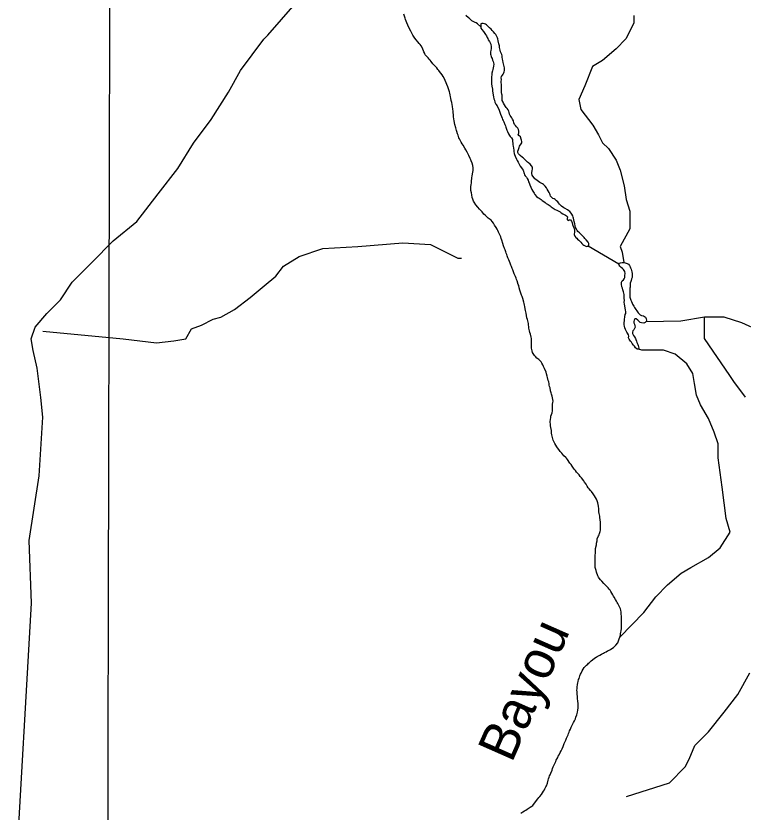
# Model space of a CAD drawing. Extents: x 3192927 to 3230760, y 831141 to 856475.
# Drawn here: x 3202099 to 3203997, y 838498 to 840576 of the extents above; entities that cross this region are included whole.
import ezdxf

# ---------------------------------------------------------------- set-up
doc = ezdxf.new("R2010")
doc.units = 0
for name, color, linetype in [('V-GRID-MAJR', 7, 'Continuous'), ('V-RIVR-IDEN', 7, 'Continuous'), ('V-TOPO-SHOR', 7, 'Continuous')]:
    doc.layers.add(name, color=color, linetype=linetype)

msp = doc.modelspace()

# ---------------------------------------------------------------- linework, layer by layer
at = {"layer": 'V-GRID-MAJR'}
msp.add_spline([(3202335.2, 836536.2), (3202348.4, 842596.7), (3202361.7, 848659.1), (3202374.9, 854721.5), (3202374.9, 854723.4)], degree=3, dxfattribs=at)
at = {"layer": 'V-TOPO-SHOR'}
msp.add_line((3203672.2, 839927.9), (3203592.4, 839974.9), dxfattribs=at)
for points in [[(3202099.2, 838328.4), (3202139.5, 839043.4), (3202134.2, 839206.8), (3202159.6, 839375.4), (3202169.7, 839528.6), (3202164.6, 839579.7), (3202154.3, 839656.3), (3202144, 839702.2), (3202138.9, 839732.9), (3202149.1, 839763.5), (3202179.7, 839799.3), (3202215.4, 839835.1), (3202246, 839881.1), (3202297.1, 839932.2), (3202353.2, 839988.4), (3202414.4, 840039.5), (3202470.6, 840111.1), (3202521.6, 840177.5), (3202562.4, 840243.9), (3202608.3, 840305.3), (3202654.2, 840376.8), (3202684.8, 840433), (3202746, 840514.8), (3202756.2, 840525), (3202827.7, 840606.8)], [(3203197.5, 840439.8), (3203190.9, 840447.4), (3203187.5, 840450.9), (3203182.7, 840456.6), (3203179.9, 840460.4), (3203177.9, 840462.7), (3203174.5, 840466.1), (3203167.3, 840474.3), (3203165.9, 840477.2), (3203163.9, 840482.2), (3203159.8, 840491.6), (3203156.5, 840497.8), (3203154.1, 840501), (3203151.3, 840503.9), (3203140.3, 840517.8), (3203134.9, 840525.5), (3203130, 840535.7), (3203123.7, 840546.8), (3203117.3, 840561.6), (3203115.5, 840566.4), (3203114.8, 840569.7), (3203111.7, 840579.8)], [(3203312.2, 840547.1), (3203304, 840555.3), (3203300.1, 840557.3), (3203297.2, 840558.4), (3203288.5, 840563.1), (3203282.7, 840568.6), (3203280.2, 840570.5), (3203273.6, 840576.7)], [(3203711.2, 840576.8), (3203711.3, 840556.4), (3203690.9, 840515.5), (3203665.3, 840490), (3203629.6, 840459.3), (3203604.1, 840444), (3203583.7, 840392.9), (3203568.4, 840357.1), (3203573.5, 840331.6), (3203604.2, 840290.8), (3203619.6, 840265.2), (3203629.8, 840244.8), (3203645.1, 840229.5), (3203665.6, 840198.9), (3203675.8, 840173.4), (3203686.1, 840132.5), (3203691.2, 840096.8), (3203701.4, 840066.1), (3203701.5, 840035.5), (3203701.5, 840020.2), (3203676, 839974.2), (3203681.1, 839958.9), (3203685.4, 839931.9)], [(3203412, 840232.1), (3203413.4, 840235.5), (3203418, 840241.9), (3203419, 840244.8), (3203419, 840248.3), (3203418.5, 840251.4), (3203417.6, 840254.3), (3203415.7, 840259.8), (3203411.9, 840263.2), (3203410.2, 840266), (3203411.6, 840269.4), (3203411.6, 840275.3), (3203410.5, 840279.4), (3203409.3, 840282.3), (3203405.7, 840285.9), (3203402.9, 840289.5), (3203400.2, 840292.1), (3203398.1, 840296.9), (3203397.6, 840301.4), (3203395.3, 840306), (3203393.1, 840309.3), (3203391.5, 840312.2), (3203388.6, 840315.8), (3203387, 840319.1), (3203386, 840323.2), (3203385.3, 840326.8), (3203383.4, 840330.6), (3203381, 840334.2), (3203378.9, 840336.8), (3203377, 840339.4), (3203374.4, 840343.3), (3203371.8, 840347.8), (3203370.3, 840350.7), (3203368.4, 840354.5), (3203368, 840358.1), (3203368, 840364.1), (3203367.8, 840368.4), (3203366.8, 840371.7), (3203366.1, 840375.5), (3203365.9, 840379.3), (3203366.4, 840382.4), (3203366.4, 840386.7), (3203366.4, 840391.3), (3203366.2, 840394.6), (3203366, 840397.7), (3203365.7, 840401.1), (3203365.7, 840404.7), (3203366, 840409.9), (3203365.8, 840413.7), (3203366.7, 840417.1), (3203368.6, 840420.9), (3203370.6, 840424), (3203372, 840426.8), (3203373.2, 840429.7), (3203373.9, 840432.8), (3203374.4, 840436.6), (3203374.4, 840440), (3203373.3, 840444), (3203371.6, 840450.5), (3203370.9, 840454.1), (3203369.7, 840459.3), (3203368.8, 840463.1), (3203368.1, 840467.7), (3203367.6, 840471.5), (3203366.9, 840474.6), (3203365, 840478.7), (3203363.3, 840482), (3203362.4, 840486.1), (3203361.7, 840489.4), (3203361.5, 840493.5), (3203360.8, 840497.8), (3203359.6, 840502.8), (3203357.7, 840510.2), (3203356.5, 840515.7), (3203355.6, 840518.8), (3203354.4, 840521.7), (3203351.3, 840526.7), (3203348.7, 840530), (3203345.1, 840534.1), (3203342, 840537.7), (3203339.4, 840540.8), (3203335.1, 840544.9), (3203332.8, 840547), (3203330.4, 840549.2), (3203327, 840552.1), (3203324.4, 840553.8), (3203321.6, 840555.2), (3203318.5, 840555.7), (3203315.3, 840555.7), (3203312.5, 840554.5), (3203312.2, 840551.4), (3203312.2, 840547.1), (3203312.7, 840543.5), (3203315.1, 840539.9), (3203318.9, 840535.2), (3203322.9, 840530.1), (3203324.8, 840527.5), (3203327.2, 840523.4), (3203328.8, 840519.6), (3203330.3, 840516.5), (3203331.7, 840512.9)], [(3203331.7, 840512.9), (3203335, 840508.4), (3203336.9, 840505.5), (3203338.3, 840502.1), (3203339, 840494.5), (3203339, 840490.2), (3203338.3, 840485.7), (3203337.8, 840482.3), (3203337.3, 840479), (3203337.8, 840475.9), (3203338.2, 840472.8), (3203339.2, 840469.9), (3203340.1, 840467), (3203341.6, 840464.2), (3203342.7, 840460.1), (3203342.9, 840459.9)], [(3203342.9, 840459.9), (3203344.4, 840457), (3203345.6, 840453.2), (3203346.1, 840449.8), (3203345.6, 840444.3), (3203343.6, 840436), (3203342.7, 840432.4), (3203341.4, 840426), (3203341.2, 840422.2), (3203340.5, 840416.9), (3203340, 840408.3), (3203340.2, 840402.3), (3203340.4, 840398.5), (3203341.3, 840392.3), (3203342.5, 840384.2), (3203343.2, 840379.4), (3203343.9, 840374.6), (3203344.9, 840368.9), (3203345.8, 840364.1), (3203346.7, 840359.1), (3203347.7, 840356), (3203349.1, 840350.7), (3203351.9, 840345.7), (3203354.8, 840340.7), (3203360, 840329.7), (3203361.2, 840326.8), (3203363.6, 840318.9), (3203365.9, 840313.2), (3203367.8, 840309.1), (3203369.2, 840305.3), (3203370.7, 840302.5), (3203372.1, 840298.9), (3203375.2, 840291.9), (3203376.6, 840288.6), (3203378, 840285.5), (3203380.6, 840277.4), (3203381.8, 840274), (3203384.4, 840268.3), (3203387, 840263.5), (3203389.2, 840261.1), (3203392.7, 840257.7), (3203394.9, 840253), (3203395.3, 840248.2), (3203395.6, 840243.9), (3203396, 840239.3), (3203396.7, 840235.3), (3203397.4, 840230.7), (3203398.6, 840225), (3203398.8, 840221.7), (3203399.1, 840216.9), (3203400, 840213.8), (3203401.7, 840209.5), (3203405.5, 840202.1), (3203407.6, 840198.2), (3203409.7, 840193.7), (3203413, 840187), (3203415.2, 840183.4), (3203418.8, 840178.9), (3203420.4, 840176.2), (3203422.6, 840172.9), (3203425.2, 840164), (3203426.3, 840161.2), (3203428.2, 840158.3), (3203431.3, 840155), (3203433.7, 840151.6), (3203435.8, 840146.8), (3203437, 840142.8), (3203438.2, 840139.7), (3203439.9, 840135.1), (3203442.7, 840128.4), (3203445.6, 840122.4), (3203447.7, 840118.1), (3203449.4, 840115.5), (3203451.3, 840112.9), (3203453.2, 840109.8), (3203457.9, 840104.5), (3203461.5, 840101.6), (3203464.3, 840099.9), (3203469.4, 840096.3), (3203472.7, 840094.2), (3203476.5, 840091.3), (3203480.1, 840088.4), (3203482.9, 840086.5), (3203487.7, 840083.2), (3203492.9, 840080), (3203495.8, 840077.6), (3203498.7, 840075.7), (3203503.7, 840072.6), (3203506.5, 840070.9), (3203511, 840068.5), (3203515.6, 840066.1), (3203519.1, 840064), (3203522.2, 840062), (3203526.5, 840059.4), (3203530.1, 840057.5), (3203533.2, 840055.8), (3203535.8, 840053.9), (3203538.4, 840051.5), (3203537.5, 840047.2), (3203537.7, 840044.1), (3203540.1, 840041.9)], [(3203331.9, 840047.8), (3203326.9, 840052.1), (3203324.5, 840054.8), (3203320.5, 840058.4), (3203315.5, 840064.3), (3203311.4, 840068.4), (3203309.3, 840071.3), (3203304.5, 840076.3), (3203299.3, 840083), (3203295.3, 840089.5), (3203293.6, 840092.6), (3203291.5, 840097.4), (3203290.1, 840102.2), (3203288.7, 840109.1), (3203287.7, 840113.6), (3203286.5, 840119.8), (3203286.1, 840126), (3203286.3, 840130.3), (3203286.8, 840135.1), (3203287.6, 840140.4), (3203288.3, 840145.8), (3203288.5, 840150.1), (3203289.3, 840153.7), (3203290, 840157.8), (3203290.7, 840163.7), (3203291.7, 840167.8), (3203292, 840172.6), (3203292, 840178.8), (3203291.3, 840185), (3203290.1, 840191.4), (3203287.5, 840197.4), (3203286.1, 840200.5), (3203284.9, 840203.9), (3203280.9, 840211.5), (3203278.2, 840216.8), (3203276.3, 840220.4), (3203273.3, 840225.9), (3203270.2, 840230.9), (3203265.9, 840238.3), (3203264, 840241.7), (3203261.1, 840246), (3203259.2, 840249.6), (3203256.6, 840254.6), (3203255, 840257.7), (3203254, 840260.8), (3203252.8, 840264.6), (3203251.9, 840267.7), (3203250, 840273.9), (3203249.1, 840277), (3203248.1, 840280.1), (3203246.9, 840283.5), (3203244.6, 840292.6), (3203243.9, 840296.2), (3203242.5, 840302.4), (3203242, 840306), (3203241.3, 840312.9), (3203240.8, 840318.1), (3203240.1, 840323.1), (3203239.9, 840326.7), (3203239.2, 840332.2), (3203238, 840339.4), (3203237.6, 840344.2), (3203236.4, 840349.4), (3203235.2, 840354.9), (3203234, 840361.4), (3203233.1, 840364.7), (3203232.6, 840370), (3203231.9, 840373.6), (3203230.8, 840377.6), (3203228.9, 840383.1), (3203226.5, 840390.3), (3203223.9, 840396.7), (3203222, 840400.6), (3203219.1, 840407.5), (3203217.5, 840411.3), (3203214.4, 840417.3), (3203211.3, 840421.8), (3203208.2, 840426.4), (3203204.9, 840430.2), (3203203, 840432.9), (3203200.4, 840436.2), (3203197.5, 840439.8), (3203197.5, 840440)], [(3203540.1, 840041.9), (3203543, 840043.1), (3203546.1, 840043.1), (3203548.7, 840040.2), (3203550.3, 840035.9), (3203551.5, 840031.6), (3203554.4, 840024), (3203555.5, 840021.1), (3203557.2, 840015.4), (3203556.9, 840011.8), (3203555.7, 840005.6), (3203557.4, 840000.8), (3203560, 839997.5), (3203562.9, 839995.5), (3203565, 839993.1), (3203567.9, 839990.5), (3203570.5, 839988.1), (3203572.9, 839985.2), (3203575.7, 839981.9), (3203578.1, 839979.5), (3203581, 839977.3), (3203586, 839974.9), (3203588.8, 839974), (3203592.4, 839974.9), (3203594.6, 839977.1), (3203594.3, 839981.6), (3203592.2, 839985.2), (3203587.2, 839991.4), (3203584.1, 839995.2), (3203582, 839997.4), (3203578.6, 840000.7), (3203575.8, 840003.6), (3203572.2, 840006.7), (3203569.4, 840009.4), (3203565.8, 840013), (3203563.6, 840016.1), (3203561.7, 840019.2), (3203559.8, 840023.5), (3203558.4, 840027.5), (3203557.3, 840033.3), (3203556.1, 840039), (3203554.9, 840043.6), (3203554.2, 840047.6), (3203553.2, 840050.5), (3203552.1, 840053.6), (3203550.2, 840057.9), (3203548.5, 840061.2), (3203544.5, 840065.3), (3203541.8, 840067.2), (3203538.3, 840069.4), (3203532.3, 840073.5), (3203529.2, 840074.9), (3203522.8, 840079), (3203519.9, 840081.9), (3203517.5, 840084.7), (3203515.4, 840087.6), (3203513, 840090.7), (3203509.7, 840093.4), (3203505.9, 840096.5), (3203503.3, 840098.1), (3203500.4, 840099.6), (3203497.3, 840101.5), (3203494.2, 840105.3), (3203493, 840108.4), (3203492.1, 840111.6), (3203490.4, 840114.9), (3203488, 840119), (3203485.7, 840123.7), (3203483.3, 840127.3), (3203480.2, 840131.2), (3203475.9, 840135.5), (3203473.5, 840137.6), (3203469.7, 840139.6), (3203466.6, 840141), (3203462.8, 840143.4), (3203459.2, 840146.3), (3203455.9, 840148.9), (3203453.5, 840150.8), (3203451.4, 840153), (3203447.8, 840157.1), (3203445.9, 840160.4), (3203445.4, 840164), (3203445.2, 840167.3), (3203446.2, 840171.1), (3203447.2, 840176.6), (3203446.9, 840181.2), (3203445, 840184.8), (3203440.7, 840189.1), (3203436.7, 840192.4), (3203434.3, 840194.3), (3203431, 840197.5), (3203427.4, 840200.6), (3203423.6, 840204.2), (3203420.7, 840206.3), (3203414.8, 840211.1), (3203412.7, 840213.7), (3203410.5, 840216.1), (3203408.9, 840219.2), (3203408.9, 840222.4), (3203410.3, 840226.9), (3203412, 840232.1)], [(3203499.2, 839553.6), (3203499.2, 839557.2), (3203499.7, 839562.4), (3203500.6, 839566.5), (3203500.7, 839570.5), (3203498.3, 839583.7), (3203496.9, 839588.9), (3203496, 839592.3), (3203494.5, 839597.5), (3203492.9, 839604.9), (3203491.9, 839608.5), (3203490.8, 839612.3), (3203490.3, 839615.4), (3203489.4, 839620.7), (3203488.4, 839624), (3203486.5, 839632.4), (3203485.8, 839636), (3203483.9, 839641.5), (3203482.5, 839646), (3203478.2, 839655.8), (3203475.9, 839661.1), (3203474.2, 839664.9), (3203471.6, 839669.9), (3203469.9, 839672.6), (3203467.6, 839675.4), (3203463.5, 839679), (3203458.8, 839682.9), (3203454.9, 839686.5), (3203452.8, 839689.3), (3203450.9, 839691.7), (3203447.6, 839697.2), (3203445.9, 839701.3), (3203445.2, 839704.9), (3203444.5, 839708.9), (3203444.5, 839713), (3203445, 839717.3), (3203445, 839723.7), (3203444.8, 839730.4), (3203444.8, 839733.8), (3203444.1, 839737.6), (3203442, 839745.5), (3203440.6, 839749.8), (3203439.6, 839754.1), (3203438.9, 839757.4), (3203438, 839760.8), (3203437.3, 839765.1), (3203436.8, 839769.1), (3203436.4, 839772.9), (3203435.6, 839776.8), (3203433.8, 839783.5), (3203432.6, 839787.8), (3203431.6, 839794), (3203430.5, 839800.2), (3203429.3, 839807.1), (3203428.4, 839811.2), (3203427.4, 839817.6), (3203426.2, 839821), (3203425.1, 839825.5), (3203424.6, 839828.6), (3203421.8, 839837.9), (3203419.9, 839843.4), (3203418.7, 839846.8), (3203415.4, 839857.5), (3203414.4, 839860.4), (3203412.8, 839866.4), (3203411.1, 839872.1), (3203409.7, 839875.2), (3203406.9, 839884.3), (3203405.4, 839887.4), (3203404.2, 839891), (3203402.4, 839895.8), (3203399.5, 839902.2), (3203395.5, 839913.4), (3203394.1, 839916.8), (3203392.2, 839922.1), (3203391, 839925.4), (3203388.6, 839930.7), (3203385.1, 839939), (3203382.9, 839944.5), (3203381, 839950), (3203379.9, 839953.1), (3203378.7, 839956.5), (3203377.5, 839959.8), (3203375.8, 839965.3), (3203374.4, 839969.1), (3203371.8, 839976.1), (3203370.2, 839981.8), (3203367.1, 839990.4), (3203365.4, 839995), (3203364.2, 839998.8), (3203361.4, 840006.2), (3203358.8, 840011.7), (3203356.6, 840015.8), (3203355, 840018.9), (3203352.1, 840023.9), (3203348.3, 840029.9), (3203345.5, 840034.4), (3203341.9, 840039.4), (3203339.5, 840042.5), (3203336.4, 840044.7), (3203331.9, 840047.8)], [(3202169.5, 839753.3), (3202379, 839733.1), (3202465.8, 839722.9), (3202511.7, 839728.1), (3202542.4, 839733.2), (3202557.7, 839758.8), (3202583.2, 839769), (3202613.8, 839784.3), (3202634.3, 839789.5), (3202670, 839809.9), (3202710.8, 839840.6), (3202746.6, 839871.3), (3202777.2, 839896.8), (3202797.6, 839922.4), (3202838.4, 839947.9), (3202899.7, 839968.4), (3202991.6, 839973.6), (3203109.1, 839983.9), (3203180.6, 839978.9), (3203252.1, 839943.2), (3203262.3, 839943.2)], [(3203685.9, 839852.4), (3203684.9, 839855.3), (3203683.3, 839861.2), (3203682.1, 839864.8), (3203680.4, 839869.1), (3203679.2, 839876), (3203679, 839880.6), (3203681.2, 839884.4), (3203684.5, 839887), (3203686.2, 839889.6), (3203687.9, 839893.4), (3203688.4, 839898.2), (3203688.6, 839903.5), (3203687.7, 839908.5), (3203684.6, 839913.5), (3203682.2, 839916.1), (3203678.2, 839919), (3203675.3, 839922.4), (3203673.2, 839924.8), (3203672.2, 839927.9), (3203673.9, 839930.7), (3203676.8, 839931.7), (3203680.8, 839932.1), (3203685.4, 839931.9), (3203689.2, 839931.2), (3203694.5, 839929.5), (3203697.5, 839927.6), (3203700.2, 839924.7), (3203701.8, 839921.3), (3203703.2, 839918), (3203704.7, 839915.1), (3203705.9, 839911.3), (3203706.6, 839907.5), (3203707.3, 839903.9), (3203707.5, 839900.8), (3203707.2, 839897.7), (3203707.5, 839896)], [(3203707.5, 839896), (3203707, 839892.9), (3203705.5, 839889.3), (3203704.3, 839885.5), (3203703.4, 839882.2), (3203702.2, 839878.4), (3203702.2, 839875), (3203702.1, 839871.2), (3203701.9, 839868.1), (3203701.6, 839865), (3203701.2, 839861.9), (3203700.9, 839857.6), (3203700.9, 839853.8), (3203700.9, 839849.2), (3203700.9, 839845.2), (3203701.6, 839841.4), (3203702.8, 839836.3), (3203703.9, 839833.5), (3203705.1, 839830.4), (3203707.3, 839826.5), (3203708.4, 839823.7), (3203711.3, 839818.4), (3203713.4, 839814.8), (3203715.1, 839811.9), (3203717, 839809.3), (3203719.1, 839805.7), (3203722.9, 839800.5), (3203725.1, 839798.1), (3203728.2, 839795.7), (3203731.5, 839794), (3203736.8, 839792.8), (3203739.6, 839791.1), (3203742.2, 839789.4), (3203743.9, 839784.9), (3203744.6, 839781.5), (3203743.4, 839778), (3203741, 839775.3), (3203738.1, 839773.9), (3203731.2, 839774.4), (3203727.9, 839775.9), (3203724.3, 839778.7), (3203721.9, 839781.4), (3203717.4, 839785.4), (3203714.1, 839785), (3203712.4, 839781.4), (3203711.6, 839778), (3203711.4, 839774.9), (3203713.1, 839771.6), (3203714.2, 839767.3), (3203714.7, 839763.7), (3203711.8, 839756.8), (3203709.2, 839754.2), (3203708, 839750.6), (3203708, 839746.5), (3203711.1, 839741.5), (3203713.4, 839737.9), (3203715.6, 839734.3), (3203717.2, 839731.2), (3203718.9, 839727.2), (3203719.8, 839723.4), (3203721.7, 839718.1), (3203722.9, 839715.2), (3203723.9, 839711.9), (3203724.8, 839709), (3203723.6, 839705.9), (3203720, 839706.4), (3203716.2, 839709.5), (3203713.1, 839713.6), (3203710.5, 839716.9), (3203707.4, 839721), (3203705.3, 839724.4), (3203702.9, 839727.2), (3203701, 839729.9), (3203699.1, 839732.5), (3203697.9, 839735.8), (3203698.2, 839740.1), (3203697.5, 839743.5), (3203695.3, 839747.5), (3203693.7, 839750.4), (3203691.8, 839754), (3203689.9, 839757.3), (3203688, 839762.1), (3203687, 839766.2), (3203686.3, 839769.5), (3203686.6, 839775.5), (3203687.1, 839780), (3203687.1, 839783.4), (3203687.8, 839790.3), (3203689, 839796.3), (3203690.7, 839799.1), (3203690.7, 839803.7), (3203690, 839808.9), (3203689.1, 839813), (3203688.4, 839818.7), (3203687.2, 839823.7), (3203686.7, 839829), (3203687, 839832.8), (3203686.5, 839839), (3203686.1, 839843.1), (3203686.6, 839848.3), (3203685.9, 839852.4)], [(3203743.4, 839778), (3203834.5, 839780.2), (3203895.7, 839790.5), (3203946.8, 839790.5), (3203992.8, 839775.2), (3204038.8, 839754.9)], [(3204003.2, 839581.2), (3203972.5, 839622), (3203962.3, 839637.3), (3203895.8, 839734.3), (3203895.7, 839790.5)], [(3203675.2, 838954.7), (3203738.1, 839019.2), (3203768.7, 839060.1), (3203799.3, 839090.7), (3203835, 839121.4), (3203860.5, 839136.7), (3203906.5, 839162.3), (3203937.1, 839187.9), (3203962.6, 839228.8), (3203952.4, 839264.5), (3203942.1, 839346.2), (3203931.8, 839422.8), (3203931.8, 839458.6), (3203921.5, 839489.2), (3203906.2, 839524.9), (3203885.7, 839560.7), (3203875.5, 839586.2), (3203870.3, 839616.8), (3203865.2, 839642.4), (3203849.9, 839667.9), (3203819.2, 839693.4), (3203788.6, 839703.6), (3203732.4, 839703.5), (3203723.6, 839705.9)], [(3203628.1, 839100.3), (3203625, 839104.6), (3203621.5, 839108.4), (3203619.6, 839111.3), (3203617.9, 839114.6), (3203616.7, 839117.5), (3203614.8, 839121.3), (3203613.9, 839124.4), (3203612.9, 839128.7), (3203611.8, 839133.5), (3203611.1, 839136.6), (3203610.7, 839140), (3203610.8, 839143.5), (3203610.9, 839148.2), (3203610.9, 839152.4), (3203610.8, 839155.4), (3203611, 839161.3), (3203611, 839164.9), (3203610.8, 839169.1), (3203611.4, 839173.1), (3203611.8, 839176.1), (3203611.5, 839179.2), (3203611.6, 839182.3), (3203611.9, 839185.5), (3203613.9, 839195.8), (3203614.6, 839200.1), (3203615.8, 839205.6), (3203616.3, 839210.8), (3203619.7, 839219.2), (3203620.9, 839222), (3203621.8, 839224.9), (3203623.5, 839229.9), (3203624.2, 839233.5), (3203624.3, 839237.1), (3203624.3, 839241.1), (3203624.3, 839244.5), (3203624.8, 839249), (3203624.3, 839254.7), (3203623.9, 839260.5), (3203622.9, 839266.4), (3203622.7, 839270.5), (3203622, 839273.6), (3203620.8, 839277), (3203620.3, 839281.5), (3203620.1, 839284.6), (3203620.1, 839289.4), (3203619.2, 839296.1), (3203618.5, 839300.6), (3203617.3, 839305.1), (3203615.6, 839310.4), (3203613.8, 839314.9), (3203611.6, 839319), (3203609.2, 839323.5), (3203605.9, 839328.3), (3203600.9, 839334.3), (3203598.3, 839337.2), (3203595, 839341.3), (3203592.8, 839344.4), (3203590, 839348.9), (3203586.9, 839353.9), (3203583.3, 839359), (3203581, 839362.8), (3203574.8, 839370.7), (3203571.9, 839374), (3203569.1, 839377.9), (3203565.7, 839381.7), (3203562.2, 839385.5), (3203559.1, 839389.1), (3203556.2, 839392.5), (3203550.3, 839400.6), (3203547.7, 839404.7), (3203545, 839409), (3203538.6, 839417.8), (3203535.8, 839421.2), (3203533.9, 839423.6), (3203529.3, 839428.1), (3203523.4, 839434.8), (3203519.8, 839438.9), (3203517.7, 839441.8), (3203510.8, 839451.6), (3203505.1, 839460.2), (3203502.5, 839465.5), (3203501.1, 839468.3), (3203499.2, 839475.5), (3203498.5, 839478.6), (3203497.8, 839482.2), (3203496.8, 839487), (3203496.6, 839490.3), (3203496.4, 839493.9), (3203494.7, 839502), (3203494.5, 839505.8), (3203494, 839509.2), (3203493.6, 839516.6), (3203493.8, 839523.3), (3203494.6, 839527.1), (3203495.3, 839531.1), (3203496.7, 839535.7), (3203498.2, 839539.7), (3203499.4, 839545), (3203499.6, 839548.6), (3203499.2, 839553.6)], [(3203524.3, 838663.4), (3203527, 838668.9), (3203530.1, 838677.3), (3203532.8, 838682.5), (3203534.2, 838686.1), (3203536.1, 838690.9), (3203540, 838699.4), (3203541.4, 838703.3), (3203542.9, 838707.1), (3203544.1, 838710.4), (3203546, 838714.9), (3203548.2, 838719.7), (3203551.5, 838726.9), (3203554.2, 838731.6), (3203556.6, 838736.2), (3203559.2, 838741.6), (3203560.4, 838745.7), (3203562.8, 838752.1), (3203564.3, 838758.6), (3203565.5, 838763.8), (3203566.2, 838770), (3203566.2, 838776), (3203566, 838781.7), (3203565.3, 838787.9), (3203564.6, 838794.4), (3203564.2, 838799.6), (3203563.5, 838805.9), (3203563.5, 838811.6), (3203563.3, 838816.4), (3203563.5, 838819.9), (3203563.5, 838824.2), (3203565, 838831.2), (3203565.7, 838835.2), (3203566.4, 838839), (3203567.6, 838844), (3203568.6, 838846.9), (3203570.3, 838853.3), (3203572.2, 838857.9), (3203573.9, 838861), (3203576.5, 838866.7), (3203579.4, 838871.2), (3203581.8, 838875), (3203584.7, 838878.1), (3203588.3, 838881.2), (3203591.2, 838884.1), (3203593.3, 838886.5), (3203596, 838888.8), (3203600, 838892.6), (3203603.6, 838895.7), (3203609.4, 838900), (3203612.9, 838902.4), (3203615.6, 838904.1), (3203623.2, 838907.8), (3203627.5, 838910.2), (3203632.1, 838912.6), (3203635, 838914.5), (3203639.3, 838916.4), (3203643.1, 838918.5), (3203645.7, 838920.2), (3203650.3, 838922.3), (3203654.6, 838925.2), (3203658.6, 838928), (3203662.2, 838930.9), (3203664.9, 838933.3), (3203669.6, 838939.9), (3203671.6, 838944.7), (3203673.7, 838950), (3203675.2, 838954.7), (3203676.6, 838959.5), (3203677.1, 838963.1), (3203678.1, 838967.8), (3203678.8, 838971.4), (3203679.1, 838977.6), (3203679.6, 838984.8), (3203679.6, 838993.9), (3203679.4, 838998.4), (3203679.2, 839003.4), (3203679.2, 839009.1), (3203678.7, 839014.6), (3203678.5, 839019.9), (3203677.3, 839024.9), (3203676.4, 839028.5), (3203674.5, 839033.3), (3203672.6, 839037.3), (3203669.7, 839042.1), (3203668.3, 839045.2), (3203666.2, 839048.8), (3203663.8, 839052.9), (3203660.5, 839058.9), (3203658.3, 839061.7), (3203656.7, 839064.8), (3203654.3, 839069.4), (3203651.7, 839073.9), (3203649.8, 839076.8), (3203647.4, 839079.9), (3203644.5, 839083), (3203641.9, 839085.7), (3203638.4, 839089.3), (3203635.7, 839091.9), (3203632.9, 839095), (3203628.1, 839100.3)], [(3203692.5, 838539.1), (3203804.8, 838574.9), (3203845.6, 838615.8), (3203855.8, 838636.2), (3203871.1, 838672), (3203906.8, 838707.8), (3203947.7, 838758.9), (3203983.4, 838804.9), (3204014, 838861.1)], [(3203416.4, 838495.7), (3203422.1, 838498.8), (3203426.7, 838501.6), (3203429.5, 838503.5), (3203433.4, 838505.9), (3203436.2, 838507.6), (3203441.3, 838510.9), (3203445.1, 838513.3), (3203448, 838515.7), (3203450.1, 838517.8), (3203453.2, 838522.3), (3203458, 838528.8), (3203460.9, 838532.6), (3203464, 838536.1), (3203466.2, 838538.8), (3203470.5, 838544.2), (3203473.6, 838548.3), (3203476.3, 838553), (3203478.2, 838555.9), (3203479.6, 838559), (3203482, 838563.8), (3203483.5, 838566.9), (3203485.9, 838573.3), (3203488, 838581.2), (3203489.2, 838584.8), (3203490.9, 838589.5), (3203491.9, 838592.4), (3203493.1, 838595.3), (3203494.8, 838599.3), (3203498.1, 838607.4), (3203499.8, 838611.5), (3203501.5, 838615.8), (3203504.6, 838623.4), (3203508, 838630.5), (3203509.2, 838633.6), (3203513.1, 838640.8), (3203514.5, 838643.7), (3203516.9, 838647.7), (3203519.8, 838653.9), (3203521.9, 838658.4), (3203524.3, 838663.4)]]:
    msp.add_lwpolyline(points, dxfattribs=at)

# ---------------------------------------------------------------- texts
at = {"layer": 'V-RIVR-IDEN'}
msp.add_text('Bayou', height=100, rotation=66.1942, dxfattribs=at).set_placement((3203392.9, 838624.2))

doc.saveas('drawing.dxf')
